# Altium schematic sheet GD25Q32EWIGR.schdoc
size 127 x 101 mm
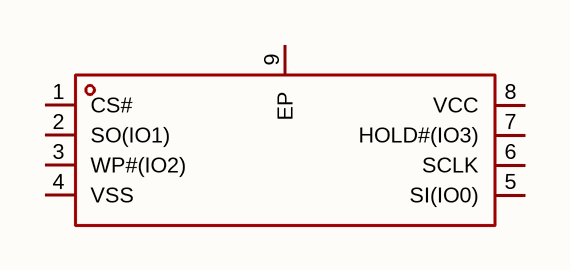
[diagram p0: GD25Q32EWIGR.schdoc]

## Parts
U?  gd25q32ewigr  [WSON-8_L6.0-W5.0-P1.27-BL-EP-1]  (value not drawn)

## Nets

Not connected (* = marked no-connect by the designer): U? 1(CS#) 2(SO(IO1)) 3(WP#(IO2)) 4(VSS) 5(SI(IO0)) 6(SCLK) 7(HOLD#(IO3)) 8(VCC) 9(EP)

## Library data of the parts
U? = gd25q32ewigr: 接口类型:SPI;存储容量:32Mbit;时钟频率(fc):133MHz;; Manufacturer: GigaDevice(兆易创新); AddInBom: yes; ModelId: 6d35dab9abb044389ea180085bc36527; ModelTransform: 237.007,196.85,0,90,0,0,0,0,0; Interface: SPI; Memory Size: 32Mbit; Clock Frequency: 133MHz; Voltage - Supply: 2.7V~3.6V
